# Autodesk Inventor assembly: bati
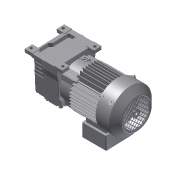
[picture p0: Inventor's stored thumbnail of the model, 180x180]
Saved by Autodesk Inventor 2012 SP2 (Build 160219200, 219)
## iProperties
Created: 2013-04
Part Number: bati
Document SubType Name: Assembly
Designer: papa
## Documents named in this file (20)
- F:\Consmec\TBPMSMA\CCF\01-CCF Cermex Moteur\01-02 Dossier Rerssources CERMEX\02-01-04 - Dessins Cermex\02-01-04-01- Dessins 3D Cermex\02-01-04-01-01 - Dessins 3D Motoreducteur\02-01-04-01-01-01 - Composants 3D Motoreducteur R43\bati.iam
- F:\Consmec\TBPMSMA\CCF\01-CCF Cermex Moteur\01-02 Dossier Rerssources CERMEX\02-01-04 - Dessins Cermex\02-01-04-01- Dessins 3D Cermex\02-01-04-01-01 - Dessins 3D Motoreducteur\02-01-04-01-01-01 - Composants 3D Motoreducteur R43\stator.ipt
- F:\Consmec\TBPMSMA\CCF\01-CCF Cermex Moteur\01-02 Dossier Rerssources CERMEX\02-01-04 - Dessins Cermex\02-01-04-01- Dessins 3D Cermex\02-01-04-01-01 - Dessins 3D Motoreducteur\02-01-04-01-01-01 - Composants 3D Motoreducteur R43\carter_reducteur.ipt
- F:\Consmec\TBPMSMA\CCF\01-CCF Cermex Moteur\01-02 Dossier Rerssources CERMEX\02-01-04 - Dessins Cermex\02-01-04-01- Dessins 3D Cermex\02-01-04-01-01 - Dessins 3D Motoreducteur\02-01-04-01-01-01 - Composants 3D Motoreducteur R43\joint plat.ipt
- F:\Consmec\TBPMSMA\CCF\01-CCF Cermex Moteur\01-02 Dossier Rerssources CERMEX\02-01-04 - Dessins Cermex\02-01-04-01- Dessins 3D Cermex\02-01-04-01-01 - Dessins 3D Motoreducteur\02-01-04-01-01-01 - Composants 3D Motoreducteur R43\couvercle.ipt
- F:\Consmec\TBPMSMA\CCF\01-CCF Cermex Moteur\01-02 Dossier Rerssources CERMEX\02-01-04 - Dessins Cermex\02-01-04-01- Dessins 3D Cermex\02-01-04-01-01 - Dessins 3D Motoreducteur\02-01-04-01-01-01 - Composants 3D Motoreducteur R43\vis HM6-16.ipt
- F:\Consmec\TBPMSMA\CCF\01-CCF Cermex Moteur\01-02 Dossier Rerssources CERMEX\02-01-04 - Dessins Cermex\02-01-04-01- Dessins 3D Cermex\02-01-04-01-01 - Dessins 3D Motoreducteur\02-01-04-01-01-01 - Composants 3D Motoreducteur R43\flasque.ipt
- F:\Consmec\TBPMSMA\CCF\01-CCF Cermex Moteur\01-02 Dossier Rerssources CERMEX\02-01-04 - Dessins Cermex\02-01-04-01- Dessins 3D Cermex\02-01-04-01-01 - Dessins 3D Motoreducteur\02-01-04-01-01-01 - Composants 3D Motoreducteur R43\carter.ipt
- F:\Consmec\TBPMSMA\CCF\01-CCF Cermex Moteur\01-02 Dossier Rerssources CERMEX\02-01-04 - Dessins Cermex\02-01-04-01- Dessins 3D Cermex\02-01-04-01-01 - Dessins 3D Motoreducteur\02-01-04-01-01-01 - Composants 3D Motoreducteur R43\vis Chc - M5 x 115-15.ipt
- F:\Consmec\TBPMSMA\CCF\01-CCF Cermex Moteur\01-02 Dossier Rerssources CERMEX\02-01-04 - Dessins Cermex\02-01-04-01- Dessins 3D Cermex\02-01-04-01-01 - Dessins 3D Motoreducteur\02-01-04-01-01-01 - Composants 3D Motoreducteur R43\rondelle M5.ipt
- F:\Consmec\TBPMSMA\CCF\01-CCF Cermex Moteur\01-02 Dossier Rerssources CERMEX\02-01-04 - Dessins Cermex\02-01-04-01- Dessins 3D Cermex\02-01-04-01-01 - Dessins 3D Motoreducteur\02-01-04-01-01-01 - Composants 3D Motoreducteur R43\vis HM5-6.ipt
- F:\Consmec\TBPMSMA\CCF\01-CCF Cermex Moteur\01-02 Dossier Rerssources CERMEX\02-01-04 - Dessins Cermex\02-01-04-01- Dessins 3D Cermex\02-01-04-01-01 - Dessins 3D Motoreducteur\02-01-04-01-01-01 - Composants 3D Motoreducteur R43\bouchon visse.ipt
- F:\Consmec\TBPMSMA\CCF\01-CCF Cermex Moteur\01-02 Dossier Rerssources CERMEX\02-01-04 - Dessins Cermex\02-01-04-01- Dessins 3D Cermex\02-01-04-01-01 - Dessins 3D Motoreducteur\02-01-04-01-01-01 - Composants 3D Motoreducteur R43\bouchon.ipt
- F:\Consmec\TBPMSMA\CCF\01-CCF Cermex Moteur\01-02 Dossier Rerssources CERMEX\02-01-04 - Dessins Cermex\02-01-04-01- Dessins 3D Cermex\02-01-04-01-01 - Dessins 3D Motoreducteur\02-01-04-01-01-01 - Composants 3D Motoreducteur R43\anneau elastique 47 x 1.75.ipt
- F:\Consmec\TBPMSMA\CCF\01-CCF Cermex Moteur\01-02 Dossier Rerssources CERMEX\02-01-04 - Dessins Cermex\02-01-04-01- Dessins 3D Cermex\02-01-04-01-01 - Dessins 3D Motoreducteur\02-01-04-01-01-01 - Composants 3D Motoreducteur R43\anneau elastique 42 x 1.75.ipt
- F:\Consmec\TBPMSMA\CCF\01-CCF Cermex Moteur\01-02 Dossier Rerssources CERMEX\02-01-04 - Dessins Cermex\02-01-04-01- Dessins 3D Cermex\02-01-04-01-01 - Dessins 3D Motoreducteur\02-01-04-01-01-01 - Composants 3D Motoreducteur R43\anneau elastique 32 x 1.2.ipt
- F:\Consmec\TBPMSMA\CCF\01-CCF Cermex Moteur\01-02 Dossier Rerssources CERMEX\02-01-04 - Dessins Cermex\02-01-04-01- Dessins 3D Cermex\02-01-04-01-01 - Dessins 3D Motoreducteur\02-01-04-01-01-01 - Composants 3D Motoreducteur R43\joints a levres 25-42-7.ipt
- F:\Consmec\TBPMSMA\CCF\01-CCF Cermex Moteur\01-02 Dossier Rerssources CERMEX\02-01-04 - Dessins Cermex\02-01-04-01- Dessins 3D Cermex\02-01-04-01-01 - Dessins 3D Motoreducteur\02-01-04-01-01-01 - Composants 3D Motoreducteur R43\rondelle elastique.ipt
- F:\Consmec\TBPMSMA\CCF\01-CCF Cermex Moteur\01-02 Dossier Rerssources CERMEX\02-01-04 - Dessins Cermex\02-01-04-01- Dessins 3D Cermex\02-01-04-01-01 - Dessins 3D Motoreducteur\02-01-04-01-01-01 - Composants 3D Motoreducteur R43\Joint a levres 17-40-7.ipt
- F:\Consmec\TBPMSMA\CCF\01-CCF Cermex Moteur\01-02 Dossier Rerssources CERMEX\02-01-04 - Dessins Cermex\02-01-04-01- Dessins 3D Cermex\02-01-04-01-01 - Dessins 3D Motoreducteur\02-01-04-01-01-01 - Composants 3D Motoreducteur R43\rondelle d'appui.ipt
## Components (36 placed, 19 different names)
1. stator:1 — Logement:20, Logement:21, Logement:26, Logement:27
2. carter_reducteur:1 — Logement:1, Logement:2, Logement:3, Logement:4, Logement:5, Logement:6, Logement:10, Logement:11, Logement:20, Logement:21, Logement:39, Logement:40, Logement:41
3. joint plat:1 — Placage:1, Placage:2, Affleurement:1
4. couvercle:1 — Placage:1, Placage:2, Affleurement:1, Logement:10, Logement:11, Logement:12, Logement:13, Logement:14, Logement:15, Logement:16, Logement:17, Logement:18, Logement:19
5. vis HM6-16:1 — Logement:15
6. vis HM6-16:4 — Logement:16
7. vis HM6-16:5 — Logement:12
8. vis HM6-16:6 — Logement:14
9. vis HM6-16:7 — Logement:18
10. vis HM6-16:8 — Logement:17
11. vis HM6-16:9 — Logement:13
12. vis HM6-16:10 — Logement:19
13. flasque:1 — Logement:22, Logement:23, Logement:24, Logement:25, Placage:3, Placage:4, Logement:26, Logement:27, Placage:9, Logement:32, Angle:1, Placage:10
14. carter:1 — Logement:32, Angle:1, Tangente:1, Tangente:2, Tangente:3
15. vis Chc - M5 x 115-15:1 — Logement:22
16. vis Chc - M5 x 115-15:2 — Logement:24
17. vis Chc - M5 x 115-15:3 — Logement:25
18. vis Chc - M5 x 115-15:4 — Logement:23
19. rondelle M5:1 — Logement:30, Placage:9, Logement:35, Tangente:2
20. vis HM5-6:1 — Logement:30, Logement:35
21. vis HM5-6:2 — Logement:31, Logement:33
22. vis HM5-6:3 — Logement:28
23. vis HM5-6:4 — Logement:29, Logement:34
24. rondelle M5:2 — Logement:31, Logement:33, Placage:10, Tangente:1
25. rondelle M5:3 — Logement:28
26. rondelle M5:4 — Logement:29, Logement:34, Tangente:3
27. bouchon visse:1 — Logement:6
28. bouchon visse:2 — Logement:5
29. bouchon:1 — Logement:4
30. anneau elastique 47 x 1.75:1 — Logement:39
31. anneau elastique 42 x 1.75:1 — Logement:1
32. anneau elastique 32 x 1.2:1 — Logement:3
33. joints a levres 25-42-7:1 — Logement:2
34. rondelle elastique:1 — Placage:3, Placage:4
35. Joint a levres 17-40-7:1 — Logement:41
36. rondelle d'appui:1 — Logement:40
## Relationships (46: Insert 35, Mate 6, Tangent 3, Flush 1, Angle 1)
- Logement:1 [Insert]: carter_reducteur:1 ↔ anneau elastique 42 x 1.75:1
- Logement:2 [Insert]: carter_reducteur:1 ↔ joints a levres 25-42-7:1
- Logement:3 [Insert]: carter_reducteur:1 ↔ anneau elastique 32 x 1.2:1
- Logement:4 [Insert]: carter_reducteur:1 ↔ bouchon:1
- Logement:5 [Insert]: carter_reducteur:1 ↔ bouchon visse:2
- Logement:6 [Insert]: carter_reducteur:1 ↔ bouchon visse:1
- Placage:1 [Mate]: joint plat:1 ↔ couvercle:1
- Placage:2 [Mate]: joint plat:1 ↔ couvercle:1
- Affleurement:1 [Flush]: joint plat:1 ↔ couvercle:1
- Logement:10 [Insert]: carter_reducteur:1 ↔ couvercle:1
- Logement:11 [Insert]: carter_reducteur:1 ↔ couvercle:1
- Logement:12 [Insert]: couvercle:1 ↔ vis HM6-16:5
- Logement:13 [Insert]: couvercle:1 ↔ vis HM6-16:9
- Logement:14 [Insert]: couvercle:1 ↔ vis HM6-16:6
- Logement:15 [Insert]: couvercle:1 ↔ vis HM6-16:1
- Logement:16 [Insert]: couvercle:1 ↔ vis HM6-16:4
- Logement:17 [Insert]: couvercle:1 ↔ vis HM6-16:8
- Logement:18 [Insert]: couvercle:1 ↔ vis HM6-16:7
- Logement:19 [Insert]: couvercle:1 ↔ vis HM6-16:10
- Logement:20 [Insert]: stator:1 ↔ carter_reducteur:1
- Logement:21 [Insert]: stator:1 ↔ carter_reducteur:1
- Logement:22 [Insert]: flasque:1 ↔ vis Chc - M5 x 115-15:1
- Logement:23 [Insert]: flasque:1 ↔ vis Chc - M5 x 115-15:4
- Logement:24 [Insert]: flasque:1 ↔ vis Chc - M5 x 115-15:2
- Logement:25 [Insert]: flasque:1 ↔ vis Chc - M5 x 115-15:3
- Placage:3 [Mate]: flasque:1 ↔ rondelle elastique:1
- Placage:4 [Mate]: flasque:1 ↔ rondelle elastique:1
- Logement:26 [Insert]: stator:1 ↔ flasque:1
- Logement:27 [Insert]: stator:1 ↔ flasque:1
- Logement:28 [Insert]: vis HM5-6:3 ↔ rondelle M5:3
- Logement:29 [Insert]: vis HM5-6:4 ↔ rondelle M5:4
- Logement:30 [Insert]: rondelle M5:1 ↔ vis HM5-6:1
- Logement:31 [Insert]: vis HM5-6:2 ↔ rondelle M5:2
- Placage:9 [Mate]: flasque:1 ↔ rondelle M5:1
- Logement:32 [Insert]: flasque:1 ↔ carter:1
- Angle:1: flasque:1 ↔ carter:1
- Logement:33 [Insert]: vis HM5-6:2 ↔ rondelle M5:2
- Logement:34 [Insert]: vis HM5-6:4 ↔ rondelle M5:4
- Logement:35 [Insert]: rondelle M5:1 ↔ vis HM5-6:1
- Placage:10 [Mate]: flasque:1 ↔ rondelle M5:2
- Tangente:1: carter:1 ↔ rondelle M5:2
- Tangente:2: carter:1 ↔ rondelle M5:1
- Tangente:3: carter:1 ↔ rondelle M5:4
- Logement:39 [Insert]: carter_reducteur:1 ↔ anneau elastique 47 x 1.75:1
- Logement:40 [Insert]: carter_reducteur:1 ↔ rondelle d'appui:1
- Logement:41 [Insert]: carter_reducteur:1 ↔ Joint a levres 17-40-7:1
